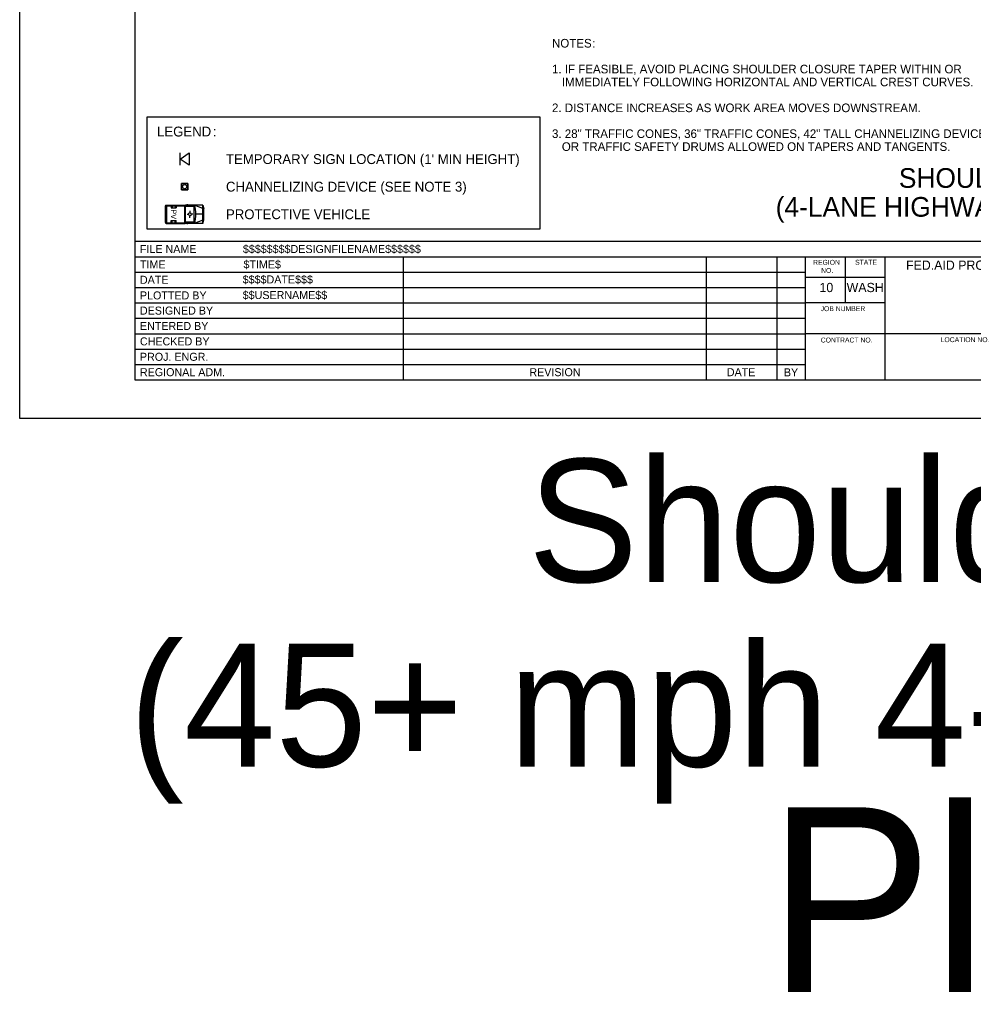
# Model space of a CAD drawing. Extents: x 99999.1 to 100096.1, y 99995 to 100010.7.
# Drawn here: x 99999.06 to 100006.81, y 99995.01 to 100002.93 of the extents above; entities that cross this region are included whole.
import ezdxf

# ---------------------------------------------------------------- set-up
doc = ezdxf.new("R2010")
doc.units = 0
for name, color, linetype in [('SH_DE_DetailHeading1Text', 7, 'Continuous'), ('SH_GI_GeneralNotesBodyText', 7, 'Continuous'), ('SH_GI_PlotLimits', 7, 'Continuous'), ('SH_GI_SheetBorder', 7, 'Continuous'), ('SH_GI_SheetLocationText', 7, 'Continuous'), ('SH_GI_SheetTextInCells', 7, 'Continuous'), ('SH_GI_TitleBlockText', 7, 'Continuous'), ('TR_WZ_PortableSignMountBlk-Wht', 7, 'Continuous'), ('TR_WZ_ProtectiveVehicle', 7, 'Continuous'), ('TR_WZ_TrafficCone', 7, 'Continuous'), ('TR_WZ_WorkZoneTextCurrent', 7, 'Continuous')]:
    doc.layers.add(name, color=color, linetype=linetype)

msp = doc.modelspace()

# ---------------------------------------------------------------- linework, layer by layer
at = {"layer": 'SH_GI_PlotLimits'}
msp.add_lwpolyline([(99999.0625, 99999.6875), (100016.0625, 99999.6875), (100016.0625, 100010.6875), (99999.0625, 100010.6875)], close=True, dxfattribs=at)
at = {"layer": 'SH_GI_SheetBorder'}
for p, q in [((100000, 100010.375), (100000, 100000)), ((100000, 100001.1259), (100015.75, 100001.1259)), ((100000, 100001.0008), (100007.4566, 100001.0008)), ((100002.179, 100001.0008), (100002.179, 100000)), ((100004.641, 100001.0008), (100004.641, 100000)), ((100005.2164, 100001.0008), (100005.2164, 100000)), ((100005.4451, 100001.0008), (100005.4451, 100000)), ((100005.7719, 100000.6255), (100005.7719, 100001.0008)), ((100006.0956, 100000), (100006.0956, 100001.0008)), ((100000, 100000.8757), (100002.1821, 100000.8757)), ((100002.1821, 100000.8757), (100005.4466, 100000.8757)), ((100006.0958, 100000.831), (100005.4466, 100000.831)), ((100000, 100000.7506), (100002.1821, 100000.7506)), ((100002.1821, 100000.7506), (100005.4466, 100000.7506)), ((100000, 100000.6255), (100005.4466, 100000.6255)), ((100006.0958, 100000.6255), (100005.4466, 100000.6255)), ((100000, 100000.5004), (100005.4466, 100000.5004)), ((100000, 100000.3753), (100005.4466, 100000.3753)), ((100007.4566, 100000.3753), (100005.4466, 100000.3753)), ((100000, 100000.2502), (100005.4466, 100000.2502)), ((100000, 100000.1251), (100005.4466, 100000.1251)), ((100000, 100000), (100015.75, 100000))]:
    msp.add_line(p, q, dxfattribs=at)
at = {"layer": 'TR_WZ_PortableSignMountBlk-Wht'}
msp.add_line((100000.3682, 100001.7439), (100000.3682, 100001.8439), dxfattribs=at)
msp.add_lwpolyline([(100000.3682, 100001.7938), (100000.44, 100001.8439), (100000.44, 100001.7439)], close=True, dxfattribs=at)
at = {"layer": 'TR_WZ_ProtectiveVehicle'}
for p, q in [((100000.248, 100001.2779), (100000.248, 100001.4138)), ((100000.2514, 100001.4184), (100000.2547, 100001.4184)), ((100000.2547, 100001.2733), (100000.2547, 100001.4184)), ((100000.2552, 100001.4208), (100000.4095, 100001.4208)), ((100000.2552, 100001.2708), (100000.2552, 100001.4208)), ((100000.2596, 100001.2768), (100000.2596, 100001.4149)), ((100000.2596, 100001.4149), (100000.4052, 100001.4149)), ((100000.2944, 100001.4149), (100000.2944, 100001.3976)), ((100000.2944, 100001.3976), (100000.3356, 100001.3976)), ((100000.3026, 100001.4149), (100000.3026, 100001.3976)), ((100000.3281, 100001.4149), (100000.3281, 100001.3976)), ((100000.3356, 100001.4149), (100000.3356, 100001.3976)), ((100000.4052, 100001.2768), (100000.4052, 100001.4149)), ((100000.4095, 100001.2708), (100000.4095, 100001.4208)), ((100000.4116, 100001.2708), (100000.4116, 100001.4208)), ((100000.5533, 100001.4208), (100000.4116, 100001.4208)), ((100000.4811, 100001.4092), (100000.4116, 100001.4092)), ((100000.4309, 100001.423), (100000.4224, 100001.423)), ((100000.4737, 100001.4092), (100000.4811, 100001.4208)), ((100000.4811, 100001.2708), (100000.4811, 100001.4208)), ((100000.4824, 100001.2708), (100000.4824, 100001.4208)), ((100000.5533, 100001.3934), (100000.4824, 100001.4208)), ((100000.5533, 100001.2708), (100000.5533, 100001.4208)), ((100000.5533, 100001.4208), (100000.5602, 100001.3906)), ((100000.5602, 100001.3011), (100000.5602, 100001.3906)), ((100000.248, 100001.3564), (100000.2547, 100001.3536)), ((100000.248, 100001.3353), (100000.2547, 100001.3381)), ((100000.2498, 100001.3458), (100000.2529, 100001.3458)), ((100000.2514, 100001.3437), (100000.2514, 100001.348)), ((100000.424, 100001.3464), (100000.4352, 100001.3461)), ((100000.4366, 100001.3461), (100000.4366, 100001.3461)), ((100000.4466, 100001.3747), (100000.4468, 100001.3634)), ((100000.4471, 100001.3161), (100000.4471, 100001.3282)), ((100000.4698, 100001.3457), (100000.4603, 100001.3458)), ((100000.5533, 100001.3458), (100000.4963, 100001.3458)), ((100000.5533, 100001.2708), (100000.5602, 100001.3011)), ((100000.2514, 100001.2733), (100000.2547, 100001.2733)), ((100000.2552, 100001.2708), (100000.4095, 100001.2708)), ((100000.2596, 100001.2768), (100000.4052, 100001.2768)), ((100000.2944, 100001.2941), (100000.3356, 100001.2941)), ((100000.2944, 100001.2768), (100000.2944, 100001.2941)), ((100000.3026, 100001.2768), (100000.3026, 100001.2941)), ((100000.3281, 100001.2768), (100000.3281, 100001.2941)), ((100000.3356, 100001.2768), (100000.3356, 100001.2941)), ((100000.4811, 100001.2825), (100000.4116, 100001.2825)), ((100000.5533, 100001.2708), (100000.4116, 100001.2708)), ((100000.4309, 100001.2687), (100000.4224, 100001.2687)), ((100000.4811, 100001.2708), (100000.4721, 100001.2825)), ((100000.5533, 100001.2983), (100000.4824, 100001.2708))]:
    msp.add_line(p, q, dxfattribs=at)
for centre, major_axis, start_param, end_param in [((100000.2514, 100001.4138), (0, 0.00458), 0, 1.570796), ((100000.3812, 100001.3459), (0, 0.1574), 4.215667, 5.208926), ((100000.2514, 100001.2779), (0, -0.00458), 4.712389, 6.283185)]:
    msp.add_ellipse(centre, major_axis=major_axis, ratio=0.73155, start_param=start_param, end_param=end_param, dxfattribs=at)
for centre, major_axis in [((100000.2514, 100001.3458), (0, -0.00211)), ((100000.4471, 100001.3458), (0, -0.0144))]:
    msp.add_ellipse(centre, major_axis=major_axis, ratio=0.73155, dxfattribs=at)
at = {"layer": 'TR_WZ_TrafficCone'}
for points in [[(100000.4308, 100001.5966), (100000.4308, 100001.5432), (100000.3775, 100001.5432), (100000.3775, 100001.5966), (100000.4308, 100001.5966)], [(100000.3775, 100001.5966), (100000.3775, 100001.5432), (100000.4308, 100001.5432), (100000.4308, 100001.5966), (100000.3775, 100001.5966)]]:
    msp.add_lwpolyline(points, dxfattribs=at)
msp.add_circle((100000.4041, 100001.5699), 0.0167, dxfattribs=at)
at = {"layer": 'TR_WZ_WorkZoneTextCurrent'}
msp.add_lwpolyline([(100000.1, 100002.1379), (100003.2886, 100002.1379), (100003.2886, 100001.2259), (100000.1, 100001.2259)], close=True, dxfattribs=at)

# ---------------------------------------------------------------- texts
at = {"layer": 'SH_DE_DetailHeading1Text'}
for s, p in [('SHOULDER CLOSURE', (100006.2068, 100001.5606)), ('(4-LANE HIGHWAYS, 40 MPH OR LESS)', (100005.2059, 100001.3259))]:
    msp.add_text(s, height=0.16, rotation=360, dxfattribs=at).set_placement(p)
at = {"layer": 'SH_GI_GeneralNotesBodyText'}
for s, p in [('NOTES', (100003.3886, 100002.7006)), (':', (100003.7161, 100002.7006)), ('1. IF FEASIBLE, AVOID PLACING SHOULDER CLOSURE TAPER WITHIN OR ', (100003.3886, 100002.4906)), ('IMMEDIATELY FOLLOWING HORIZONTAL AND VERTICAL CREST CURVES.', (100003.4686, 100002.3856)), ('2. DISTANCE INCREASES AS WORK AREA MOVES DOWNSTREAM.', (100003.3886, 100002.1756)), ('3. 28" TRAFFIC CONES, 36" TRAFFIC CONES, 42" TALL CHANNELIZING DEVICES, ', (100003.3886, 100001.9656)), ('OR TRAFFIC SAFETY DRUMS ALLOWED ON TAPERS AND TANGENTS.', (100003.4686, 100001.8606))]:
    msp.add_text(s, height=0.07, rotation=360, dxfattribs=at).set_placement(p)
at = {"layer": 'SH_GI_SheetLocationText'}
for s, height, p in [('Shoulder Closure', 1, (100003.1945, 99998.3571)), ('(45+ mph 4-Lane Highways)', 1, (99999.9523, 99996.8571)), ('Plot 1', 1.5, (100005.1422, 99995.0267))]:
    msp.add_text(s, height=height, dxfattribs=at).set_placement(p)
at = {"layer": 'SH_GI_SheetTextInCells'}
for s, height, p in [('FILE NAME', 0.06505, (100000.041, 100001.0308)), ('TIME', 0.06505, (100000.041, 100000.9057)), ('REGION', 0.04003, (100005.5099, 100000.9352)), ('NO.', 0.04003, (100005.5752, 100000.869)), ('STATE', 0.04003, (100005.8511, 100000.9357)), ('FED.AID PROJ.NO.', 0.07506, (100006.2652, 100000.8945)), ('DATE', 0.06505, (100000.041, 100000.7806)), ('10', 0.07506, (100005.5621, 100000.7131)), ('WASH', 0.07506, (100005.7826, 100000.7131)), ('PLOTTED BY', 0.06505, (100000.041, 100000.6538)), ('DESIGNED BY', 0.065052, (100000.041, 100000.5304)), ('JOB NUMBER', 0.04003, (100005.5712, 100000.5587)), ('ENTERED BY', 0.06505, (100000.041, 100000.4053)), ('CHECKED BY', 0.06505, (100000.041, 100000.2802)), ('CONTRACT NO.', 0.040032, (100005.5725, 100000.3037)), ('LOCATION NO.', 0.040032, (100006.5465, 100000.3067)), ('PROJ. ENGR.', 0.065052, (100000.041, 100000.1551)), ('REGIONAL ADM.', 0.065052, (100000.041, 100000.03)), ('REVISION', 0.06505, (100003.2048, 100000.03)), ('DATE', 0.06505, (100004.8091, 100000.03)), ('BY', 0.06505, (100005.2725, 100000.0285))]:
    msp.add_text(s, height=height, dxfattribs=at).set_placement(p)
at = {"layer": 'SH_GI_TitleBlockText'}
for s, height, p in [('$$$$$$$$DESIGNFILENAME$$$$$$', 0.065052, (100000.8775, 100001.0308)), ('$TIME$', 0.06505, (100000.882, 100000.9059)), ('$$$$DATE$$$', 0.065052, (100000.8759, 100000.7835)), ('$$USERNAME$$', 0.065052, (100000.8759, 100000.6567))]:
    msp.add_text(s, height=height, dxfattribs=at).set_placement(p)
at = {"layer": 'TR_WZ_ProtectiveVehicle'}
msp.add_text('PV', height=0.045, rotation=270, dxfattribs=at).set_placement((100000.2925, 100001.3862))
at = {"layer": 'TR_WZ_WorkZoneTextCurrent'}
for s, p in [('LEGEND', (100000.18, 100001.9779)), (':', (100000.6328, 100001.9779)), ("TEMPORARY SIGN LOCATION (1' MIN HEIGHT)", (100000.74, 100001.7539)), ('CHANNELIZING DEVICE (SEE NOTE 3)', (100000.74, 100001.5299)), ('PROTECTIVE VEHICLE', (100000.74, 100001.3059))]:
    msp.add_text(s, height=0.08, rotation=360, dxfattribs=at).set_placement(p)

doc.saveas('drawing.dxf')
